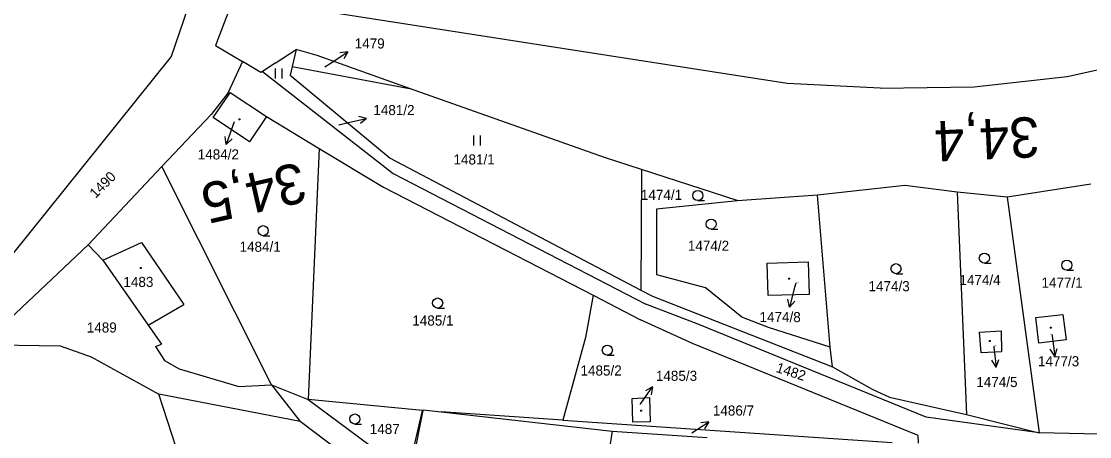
# Model space of a CAD drawing. Extents: x -805730 to -804640, y -1150889 to -1150366.
# Drawn here: x -805353.5 to -805194.5, y -1150620.5 to -1150558.7 of the extents above; entities that cross this region are included whole.
import ezdxf

# ---------------------------------------------------------------- set-up
doc = ezdxf.new("R2010")
doc.units = 0
for name, color, linetype in [('Default', 7, 'Continuous'), ('kilometráž - vrstava 7', 7, 'Continuous'), ('kn_celek - Cisla parcel pomocna', 7, 'Continuous'), ('kn_celek - Cisla pozemkovych parcel', 7, 'Continuous'), ('kn_celek - Cisla stavebnich parcel', 7, 'Continuous'), ('kn_celek - Hranice parcel', 7, 'Continuous'), ('kn_celek - Vnitrni kresby', 7, 'Continuous'), ('kn_celek - Znacky budov', 7, 'Continuous'), ('kn_celek - Znacky kultur', 7, 'Continuous')]:
    doc.layers.add(name, color=color, linetype=linetype)

# ---------------------------------------------------------------- blocks, each defined once
blk = doc.blocks.new('304')
at = {"layer": 'Default'}
blk.add_line((-0.1, 0), (9.9, 0), dxfattribs=at)
blk.add_circle((-0.1, 7.5), 7.5, dxfattribs=at)
blk = doc.blocks.new('306')
at = {"layer": 'Default'}
for p, q in [((-5.2, 0), (-5.2, 15)), ((4.8, 0), (4.8, 15))]:
    blk.add_line(p, q, dxfattribs=at)
blk = doc.blocks.new('402')
at = {"layer": 'Default'}
for p, q in [((-0.8, 0.8), (0.7, 0.8)), ((-0.8, 0.8), (-0.8, -0.7)), ((0.7, 0.8), (0.7, -0.7)), ((0.7, -0.7), (-0.8, -0.7))]:
    blk.add_line(p, q, dxfattribs=at)
blk = doc.blocks.new('Z61')
at = {"layer": 'Default'}
for p, q in [((0, 0), (30, 0)), ((30, 0), (19.2, 5.3)), ((30, 0), (19.2, -5.3))]:
    blk.add_line(p, q, dxfattribs=at)

msp = doc.modelspace()

# ---------------------------------------------------------------- linework, layer by layer
at = {"layer": 'kn_celek - Cisla parcel pomocna'}
for p, q in [((-805308.33, -1150565.43), (-805307.42, -1150564.84)), ((-805321.84, -1150573.62), (-805322.03, -1150574.18)), ((-805306.25, -1150574.07), (-805305.05, -1150573.79)), ((-805238.25, -1150597.61), (-805238.43, -1150598.3)), ((-805200.14, -1150605.26), (-805200.11, -1150605.51)), ((-805208.78, -1150607), (-805208.77, -1150607.14)), ((-805261.48, -1150615.71), (-805261.34, -1150615.52))]:
    msp.add_line(p, q, dxfattribs=at)
at = {"layer": 'kn_celek - Hranice parcel'}
for p, q in [((-805321.88, -1150555.04), (-805324.61, -1150562.25)), ((-805239.54, -1150567.94), (-805321.88, -1150555.04)), ((-805328.74, -1150556.64), (-805331.2, -1150563.91)), ((-805324.61, -1150562.25), (-805320.59, -1150564.67)), ((-805315.73, -1150564.89), (-805312.63, -1150562.86)), ((-805312.63, -1150562.86), (-805313.2, -1150565.37)), ((-805309.48, -1150563.77), (-805312.63, -1150562.86)), ((-805331.2, -1150563.91), (-805354.86, -1150593.35)), ((-805295.74, -1150568.65), (-805309.48, -1150563.77)), ((-805197.9, -1150566.86), (-805184.24, -1150563.91)), ((-805320.59, -1150564.67), (-805322.76, -1150569.38)), ((-805317.89, -1150566.3), (-805320.59, -1150564.67)), ((-805315.73, -1150564.89), (-805317.62, -1150566.13)), ((-805313.2, -1150565.37), (-805313.49, -1150566.66)), ((-805313.2, -1150565.37), (-805295.74, -1150568.65)), ((-805317.62, -1150566.13), (-805317.89, -1150566.3)), ((-805317.62, -1150566.13), (-805298.18, -1150581.32)), ((-805313.49, -1150566.66), (-805298.61, -1150579.03)), ((-805211.73, -1150568.44), (-805197.9, -1150566.86)), ((-805266.74, -1150578.94), (-805295.74, -1150568.65)), ((-805225.71, -1150568.62), (-805239.54, -1150567.94)), ((-805225.71, -1150568.62), (-805211.73, -1150568.44)), ((-805322.76, -1150569.38), (-805325.28, -1150572.52)), ((-805324.98, -1150572.98), (-805322.57, -1150569.49)), ((-805322.76, -1150569.38), (-805322.57, -1150569.49)), ((-805322.57, -1150569.49), (-805322.43, -1150569.28)), ((-805322.43, -1150569.28), (-805317.05, -1150572.83)), ((-805325.28, -1150572.52), (-805332.59, -1150580.27)), ((-805319.57, -1150576.6), (-805324.98, -1150572.98)), ((-805317.05, -1150572.83), (-805319.57, -1150576.6)), ((-805317.05, -1150572.83), (-805309.17, -1150577.58)), ((-805309.17, -1150577.58), (-805310.84, -1150614.97)), ((-805309.17, -1150577.58), (-805299.62, -1150583.35)), ((-805332.59, -1150580.27), (-805343.57, -1150591.91)), ((-805316.27, -1150612.77), (-805332.59, -1150580.27)), ((-805298.61, -1150579.03), (-805261.34, -1150598.68)), ((-805261.24, -1150580.73), (-805266.74, -1150578.94)), ((-805298.18, -1150581.32), (-805260.57, -1150600.77)), ((-805261.24, -1150580.73), (-805261.34, -1150598.68)), ((-805247.01, -1150585.35), (-805261.24, -1150580.73)), ((-805299.62, -1150583.35), (-805268.44, -1150599.44)), ((-805222.04, -1150583.09), (-805235.05, -1150584.53)), ((-805214.25, -1150584.07), (-805222.04, -1150583.09)), ((-805194.37, -1150582.88), (-805206.79, -1150584.83)), ((-805235.05, -1150584.53), (-805246.94, -1150585.36)), ((-805233.16, -1150607.18), (-805235.05, -1150584.53)), ((-805206.79, -1150584.83), (-805214.25, -1150584.07)), ((-805214.25, -1150584.07), (-805212.85, -1150617.17)), ((-805206.79, -1150584.83), (-805202.04, -1150619.89)), ((-805246.96, -1150585.36), (-805259.01, -1150586.6)), ((-805259.01, -1150586.6), (-805258.98, -1150596.36)), ((-805246.96, -1150585.36), (-805247.01, -1150585.35)), ((-805246.94, -1150585.36), (-805246.96, -1150585.36)), ((-805343.57, -1150591.91), (-805359.29, -1150606.79)), ((-805343.57, -1150591.91), (-805341.38, -1150594.2)), ((-805341.38, -1150594.2), (-805334.64, -1150603.89)), ((-805242.53, -1150594.64), (-805236.43, -1150594.46)), ((-805242.35, -1150599.49), (-805242.53, -1150594.64)), ((-805236.43, -1150594.46), (-805236.25, -1150599.34)), ((-805258.98, -1150596.36), (-805251.77, -1150598.28)), ((-805268.44, -1150599.44), (-805269.55, -1150605.7)), ((-805268.44, -1150599.44), (-805261.36, -1150603.09)), ((-805261.34, -1150598.68), (-805259.61, -1150599.59)), ((-805246.31, -1150602.71), (-805251.77, -1150598.28)), ((-805236.25, -1150599.34), (-805242.35, -1150599.49)), ((-805252.68, -1150603.77), (-805260.57, -1150600.77)), ((-805259.61, -1150599.59), (-805232.81, -1150610.08)), ((-805202.55, -1150602.73), (-805198.52, -1150602.28)), ((-805198.52, -1150602.28), (-805198.01, -1150606.08)), ((-805334.64, -1150603.89), (-805332.66, -1150606.73)), ((-805253.62, -1150606.59), (-805261.36, -1150603.09)), ((-805218.86, -1150617.58), (-805252.68, -1150603.77)), ((-805242.34, -1150604.24), (-805246.31, -1150602.71)), ((-805233.16, -1150607.18), (-805242.34, -1150604.24)), ((-805202.1, -1150606.56), (-805202.55, -1150602.73)), ((-805269.55, -1150605.7), (-805272.94, -1150618.01)), ((-805210.92, -1150604.95), (-805207.69, -1150604.71)), ((-805210.7, -1150608.02), (-805210.92, -1150604.95)), ((-805207.69, -1150604.71), (-805207.65, -1150607.87)), ((-805359.29, -1150606.79), (-805347.74, -1150606.97)), ((-805347.74, -1150606.97), (-805343.1, -1150608.62)), ((-805333.53, -1150607.06), (-805332.66, -1150606.73)), ((-805333.53, -1150607.06), (-805332.2, -1150609.13)), ((-805220.03, -1150620.31), (-805253.62, -1150606.59)), ((-805232.81, -1150610.08), (-805233.16, -1150607.18)), ((-805198.01, -1150606.08), (-805202.1, -1150606.56)), ((-805343.1, -1150608.62), (-805333.04, -1150614.16)), ((-805207.65, -1150607.87), (-805210.7, -1150608.02)), ((-805332.2, -1150609.13), (-805330.04, -1150610.39)), ((-805330.04, -1150610.39), (-805321.14, -1150613.03)), ((-805232.81, -1150610.08), (-805226.92, -1150613.4)), ((-805321.14, -1150613.03), (-805316.27, -1150612.77)), ((-805316.27, -1150612.77), (-805312.03, -1150618.23)), ((-805316.27, -1150612.77), (-805310.84, -1150614.97)), ((-805226.92, -1150613.4), (-805224.33, -1150614.59)), ((-805312.03, -1150618.23), (-805333.04, -1150614.16)), ((-805329.77, -1150624.22), (-805333.04, -1150614.16)), ((-805310.84, -1150614.97), (-805295.98, -1150625.93)), ((-805293.82, -1150616.59), (-805310.84, -1150614.97)), ((-805262.61, -1150614.81), (-805260.03, -1150614.67)), ((-805262.51, -1150618.33), (-805262.61, -1150614.81)), ((-805260.03, -1150614.67), (-805259.94, -1150618.26)), ((-805224.33, -1150614.59), (-805212.85, -1150617.17)), ((-805295.98, -1150625.93), (-805293.82, -1150616.59)), ((-805293.75, -1150616.59), (-805295.53, -1150625.4)), ((-805293.82, -1150616.59), (-805293.75, -1150616.59)), ((-805293.75, -1150616.59), (-805293.73, -1150616.47)), ((-805293.73, -1150616.47), (-805291.03, -1150616.78)), ((-805272.94, -1150618.01), (-805291.03, -1150616.78)), ((-805291.03, -1150616.78), (-805265.57, -1150619.68)), ((-805303.74, -1150624.45), (-805312.03, -1150618.23)), ((-805272.94, -1150618.01), (-805223.94, -1150621.35)), ((-805259.94, -1150618.26), (-805262.51, -1150618.33)), ((-805202.04, -1150619.89), (-805218.86, -1150617.58)), ((-805212.85, -1150617.17), (-805202.04, -1150619.89)), ((-805265.57, -1150619.68), (-805268.41, -1150637.4)), ((-805265.57, -1150619.68), (-805251.46, -1150620.59)), ((-805188.96, -1150620.19), (-805202.04, -1150619.89)), ((-805220.01, -1150621.44), (-805220.03, -1150620.31))]:
    msp.add_line(p, q, dxfattribs=at)
at = {"layer": 'kn_celek - Vnitrni kresby'}
for p, q in [((-805341.38, -1150594.2), (-805335.62, -1150591.6)), ((-805335.62, -1150591.6), (-805329.34, -1150600.83)), ((-805334.64, -1150603.89), (-805329.34, -1150600.83))]:
    msp.add_line(p, q, dxfattribs=at)

# ---------------------------------------------------------------- block references
at = {"layer": 'kn_celek - Cisla parcel pomocna'}
for p, xscale, yscale, rotation in [((-805307.42, -1150564.84), 0.1, 0.10000000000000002, 32.91219000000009), ((-805322.03, -1150574.18), 0.1, 0.09999999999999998, -109.09350000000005), ((-805305.05, -1150573.79), 0.10000000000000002, 0.1, 12.984480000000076), ((-805238.43, -1150598.3), 0.09999999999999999, 0.1, -104.82219000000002), ((-805200.11, -1150605.51), 0.09999999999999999, 0.10000000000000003, -82.76579999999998), ((-805208.77, -1150607.14), 0.1, 0.09999999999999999, -83.96226000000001), ((-805261.34, -1150615.52), 0.1, 0.09999999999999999, 54.29772000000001), ((-805253.72, -1150619.92), 0.1, 0.10000000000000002, 33.69015000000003)]:
    msp.add_blockref('Z61', p, dxfattribs=dict(at, xscale=xscale, yscale=yscale, rotation=rotation))
at = {"layer": 'kn_celek - Znacky budov', "xscale": 0.1, "yscale": 0.10000000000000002}
for p in [(-805321.06, -1150573.27), (-805335.77, -1150595.36), (-805239.26, -1150596.98), (-805200.35, -1150604.24), (-805209.39, -1150606.23), (-805261.3, -1150616.62)]:
    msp.add_blockref('402', p, dxfattribs=at)
at = {"layer": 'kn_celek - Znacky kultur', "xscale": 0.1, "yscale": 0.10000000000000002}
for name, p in [('306', (-805315.18, -1150567.2)), ('306', (-805285.67, -1150577.15)), ('304', (-805252.83, -1150585.34)), ('304', (-805250.86, -1150589.59)), ('304', (-805317.51, -1150590.57)), ('304', (-805210.19, -1150594.65)), ('304', (-805197.92, -1150595.71)), ('304', (-805223.34, -1150596.23)), ('304', (-805291.55, -1150601.34)), ('304', (-805266.3, -1150608.36)), ('304', (-805303.88, -1150618.6))]:
    msp.add_blockref(name, p, dxfattribs=at)

# ---------------------------------------------------------------- texts
at = {"layer": 'kilometráž - vrstava 7'}
for s, height, rotation, p in [('34,4', 6, 182.5512, (-805202.15, -1150572.86)), ('34,5', 5.978, 192.9136, (-805312, -1150579.56))]:
    msp.add_text(s, height=height, rotation=rotation, dxfattribs=at).set_placement(p)
at = {"layer": 'kn_celek - Cisla parcel pomocna'}
for s, p in [('1479', (-805303.9, -1150562.71)), ('1481/2', (-805301.13, -1150572.62)), ('1484/2', (-805327.26, -1150579.22)), ('1474/8', (-805243.66, -1150603.43)), ('1477/3', (-805202.22, -1150610)), ('1485/3', (-805259.08, -1150612.17)), ('1474/5', (-805211.4, -1150613.1)), ('1486/7', (-805250.6, -1150617.34))]:
    msp.add_text(s, height=1.5, dxfattribs=at).set_placement(p)
at = {"layer": 'kn_celek - Cisla pozemkovych parcel'}
for s, height, p in [('1479', 0.1, (-805308.33, -1150565.4)), ('1481/2', 0.1, (-805306.25, -1150574.04)), ('1481/1', 1.5, (-805289.2, -1150579.97)), ('1474/1', 1.5, (-805261.31, -1150585.24)), ('1484/1', 1.5, (-805321.04, -1150592.96)), ('1474/2', 1.5, (-805254.32, -1150592.82)), ('1474/3', 1.5, (-805227.44, -1150598.83)), ('1474/4', 1.5, (-805213.92, -1150597.92)), ('1477/1', 1.5, (-805201.7, -1150598.31)), ('1485/1', 1.5, (-805295.33, -1150603.94)), ('1489', 1.5, (-805343.77, -1150604.98)), ('1485/2', 1.5, (-805270.3, -1150611.38)), ('1487', 1.5, (-805301.66, -1150620.08)), ('1486/7', 0.1, (-805253.72, -1150619.89))]:
    msp.add_text(s, height=height, dxfattribs=at).set_placement(p)
for s, rotation, p in [('1490', 45, (-805342.46, -1150585.08)), ('1482', 342, (-805241.32, -1150610.82))]:
    msp.add_text(s, height=1.5, rotation=rotation, dxfattribs=at).set_placement(p)
at = {"layer": 'kn_celek - Cisla stavebnich parcel'}
for s, height, p in [('1484/2', 0.1, (-805321.84, -1150573.59)), ('1483', 1.5, (-805338.32, -1150598.2)), ('1474/8', 0.1, (-805238.25, -1150597.58)), ('1477/3', 0.1, (-805200.42, -1150605.23)), ('1474/5', 0.1, (-805208.78, -1150606.97)), ('1485/3', 0.1, (-805261.48, -1150615.68))]:
    msp.add_text(s, height=height, dxfattribs=at).set_placement(p)

doc.saveas('drawing.dxf')
